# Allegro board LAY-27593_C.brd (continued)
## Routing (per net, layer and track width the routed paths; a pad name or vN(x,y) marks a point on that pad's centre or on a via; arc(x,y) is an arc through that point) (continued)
VREFH: length 2.7
  TOP w0.305: U7.37 20.5,24.35 20.57,24.42 v1(20.57,24.43)
  BOTTOM w0.61: C213.1 v1(20.57,24.43)
VREFL: length 3.4
  TOP w0.305: U7.38 21,23.79 21.65,24.43 v1(22.09,24.43)
  BOTTOM w0.61: v1(22.09,24.43) C212.1
N7254025: length 3
  BOTTOM w0.178: R200.2 63.36,52.01 J201.3
N7311373: length 8.9
  TOP w0.178: Q1.1 56.31,40.37 54.99,41.69 52.96,41.69 51.48,40.22 R9.2
  BOTTOM w0.178: R205.2 Q1.1
N7313274: length 3.5
  TOP w0.178: D4.A 60.75,39.8 R10.2
N7314056: length 70.4
  BOTTOM w0.178: R213.2 33.4,29.12 33.4,31.79 33.97,32.37 33.98,32.37 37.02,35.41 39.56,35.41 41.14,36.99 46.7,36.99 50.64,40.93 51.5,41.79 53.06,41.79 54.35,43.09 65.02,43.09 69.97,48.04 69.97,61.5 D2.C
N7314060: length 60.7
  TOP w0.178: v1(20.82,28.87) 20.32,29.37 19.05,29.37 v1(14.6,33.82)
  L3_PWR w0.178: D1.C 10.74,69.43 8.84,69.43 8.2,68.79 8.2,67.88 8.77,67.31 8.77,59.99 11.43,57.34 11.43,43.85 10.27,42.7 10.27,40.77 11.05,40 11.05,39.58 10.98,39.52 10.98,38.71 11.81,37.88 11.81,36.61 v1(14.6,33.82)
  BOTTOM w0.178: v1(20.82,28.87) 21.34,28.35 23.81,28.35 24.51,27.65 24.51,25.56 25.14,24.93 R216.2
N7317031: length 9
  TOP w0.889: U6.3 79.68,47.75 J1.1
N7317123: length 22.1
  TOP w0.178: U4.4 4.36,53.34 R3.1 4.36,55.33 7.04,58.01 10.97,58.01 13.64,55.34 13.85,55.03 13.85,51.73 12.84,50.72 v1(12.84,50.46)
  BOTTOM w0.178: J202.3 10.55,50.46 v1(12.84,50.46)
N7317135: length 2.9
  TOP w0.178: U3.2 9.89,52.83 11.73,54.67 R4.1
N7317139: length 7.7
  TOP w0.178: v1(7.97,57.44) 7.83,57.3 7.83,55.22 C3.2 R3.2
  BOTTOM w0.178: v1(7.97,57.44) 7.97,56.3 ; 7.97,56.3 D201.A ; 7.97,56.3 6.9,56.3 D200.A
N7317159: length 19.9
  TOP w0.178: v1(13.08,44.61) 13.08,44.66 12.26,45.47 12.26,50.82 12.6,51.15 12.63,51.15 13.49,52.01 13.49,54.92 13.36,55.11 12.84,55.64 10.77,55.64 10.27,55.14 10.27,54.86 R4.2 C3.1
  BOTTOM w0.178: J202.9 11.45,42.99 v1(13.08,44.61)
N7317195: length 26.3
  TOP w0.178: v1(3.68,57.58) 6.01,57.58 6.8,58.37 11.12,58.37 13.92,55.57 14.2,55.14 14.2,51.58 13.41,50.79 13.41,50.22 13.04,49.85 v1(13.04,45.51)
  BOTTOM w0.178: D200.C 3.68,56.37 v1(3.68,57.58) ; J202.7 13.02,45.53 v1(13.04,45.51)
N7317203: length 11.4
  BOTTOM w0.178: 14,50.23 13.22,51.01 13.22,53.36 12.29,54.29 D201.C ; 14,50.23 D202.A ; 14,50.23 14,50.11 13.2,49.31 12.82,49.31 11.58,48.07 J202.5
N7317219: length 2.8
  TOP w0.178: U4.3 v1(5.2,51.73)
  BOTTOM w0.178: J202.4 5.2,50.85 v1(5.2,51.73)
N7317435: length 1.8
  TOP w0.178: R11.2 79.8,36.51 U6.2
N7330976: length 9
  TOP w0.889: J1.2 77.14,47.75 U6.4
N7332359: length 2.1
  TOP w0.178: R7.2 5.76,42.67 U4.2
N7333527: length 4.5
  TOP w0.178: v1(12.92,54.75) 12.19,54.02 12.19,52.88 U3.1
  BOTTOM w0.178: D202.C 14.09,54.37 13.71,54.75 v1(12.92,54.75)
N7413835: length 2
  TOP w0.305: U5.1 43.36,42.27 43.81,41.82 C5.1
N7432331: length 3.7
  TOP w0.508: R14.2 R13.1
N7432681: length 3.7
  TOP w0.508: R15.2 R14.1
N7432685: length 8.3
  TOP w0.508: R12.2 62,30.01 60.96,28.97 R15.1
N7470913: length 19.8
  BOTTOM w0.635: 50.77,16.06 U200.7 47.47,16.06 ; 50.64,13.52 U200.5 47.47,13.52 ; 50.64,14.79 U200.6 47.47,14.79 ; 50.69,17.33 U200.8 47.52,17.33
  BOTTOM w0.889: C217.2 52.04,17.46 ; C217.2 R217.2 ; C217.2 51.02,19.37 C218.2 50.75,17.38 50.69,17.33
N7471057: length 2.1
  BOTTOM w0.635: C217.1 53.97,17.42 U200.1
N7471061: length 14.4
  BOTTOM w0.635: U200.2 55.39,16.06 55.75,16.42 55.75,20.36 54.86,21.25 54,21.25 R217.1 53.97,22.39 53.59,22.77 50.67,22.77 C216.2 50.75,22.44 R218.2
N7471069: length 7.2
  BOTTOM w0.889: D203.C 47.36,22.64 C216.1 48.81,22.44 R218.1 C218.1
N7676044: length 12.1
  TOP w0.508: U8.1 44.38,9.01 44.77,8.62 44.77,7.5 44.38,7.11 U8.3
  TOP w0.762: C24.1 43.82,9.03 U8.1
  TOP w0.889: C24.1 C23.1 40.18,12.05 39.34,12.89 J6.2
N7706869: length 4
  TOP w0.178: U7.25 12.19,24.42 10.38,26.22 Y1.1
N7742135: length 2.2
  TOP w0.762: D5.C 54.78,9.78 55.5,9.07 D6.1
N7743508: length 3.7
  TOP w0.762: R24.1 45.89,6.57 U8.4 47.61,7.11 R23.2
N7798929: length 43.4
  L3_PWR w0.178: v1(25.12,28.5) 26.05,28.5 26.67,29.12 27.49,29.12 27.94,28.67 27.94,27.47 29.61,25.79 v1(30.16,25.79)
  BOTTOM w0.229: R210.2 18.51,34.1 16.03,34.1 15.44,33.51 15.44,29.81 16,29.25 16.97,29.25 17.02,29.25 18.4,29.25 19.13,29.97 21.33,29.97 22.06,29.25 24.06,29.25 24.8,28.5 v1(25.12,28.5)
  BOTTOM w0.381: v1(30.16,25.79) 32.1,25.79 32.51,26.2 33.65,26.2 35.3,27.85 39.31,27.85 40.7,29.25 43.13,29.25 J4.1
N7799438: length 27.3
  BOTTOM w0.229: J3.1 40.11,27.49 38.8,26.18 36.34,26.18 34.46,24.3 28.9,24.3 27.89,25.31 25.52,25.31 24.89,25.94 24.89,27.81 23.94,28.76 21.79,28.76 21.08,29.48 19.91,29.48 R214.2
N7817781: length 5.9
  TOP w0.178: Y1.2 14.7,23.68 15,23.38 U7.26
N7845653: length 4.8
  TOP w0.889: J8.1 59.53,7.28 57.27,7.28 56.3,7.06 D6.3
N7881250: length 23.4
  TOP w0.508: J5.1 62.86,15.78 v1(65.15,15.78) v1(65.15,14.92)
  L3_PWR w0.508: v1(65.15,14.92) v1(65.15,15.78) 65.15,15.94 68.42,19.21 72.39,19.21 76.45,23.28 76.45,25.03 BT200.1
N8061225: length 18.1
  TOP w0.178: D3.C 33.7,43.55 32.89,44.36 26.29,44.36 26.16,44.23 23.49,44.23 23.36,44.36 22.2,44.36 21.84,44.72 v1(21.84,44.74)
  BOTTOM w0.178: v1(21.84,44.74) 21.84,44.69 21.64,44.49 21.64,42.42 20.95,41.74 20.95,40.62 21.22,40.36 21.22,40.23 R204.2
N8098939: length 12.5
  TOP w0.178: v1(27.06,41.55) 27.06,41.58 27.61,42.12 SW1.1 25.07,43.11 24.36,43.82 20.01,43.82 19.3,43.11 SW1.2
  BOTTOM w0.178: v1(27.06,41.55) R203.2

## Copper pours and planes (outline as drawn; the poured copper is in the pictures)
GND on TOP: 36.19,10.27 1.27,10.27 1.27,87.73 84.73,87.73 84.73,21.12 74.93,21.12 74.93,8.8 70.99,8.8 70.99,0.93 36.19,0.93 ; 12 cut-outs
GND on BOTTOM: 36.19,10.27 1.27,10.27 1.27,87.73 84.73,87.73 84.73,21.12 74.93,21.12 74.93,8.8 70.99,8.8 70.99,0.93 36.19,0.93 ; 20 cut-outs
GND on L2_GND: 74.04,1.69 36.72,1.69 36.69,10.44 2.03,10.44 2.03,28.61 13.08,28.61 14.47,30.01 14.47,35.85 10.66,39.66 10.66,42.33 13.2,45.38 13.71,46.01 17.27,46.01 17.9,45.38 17.9,40.3 18.92,39.28 27.56,39.28 28.44,40.42 28.44,50.96 30.22,52.74 53.59,52.74 56,54.77 56,73.57 57.65,75.35 70.1,75.35 70.1,87.41 83.97,87.41 83.97,21.12 74.04,21.12 ; 1 cut-out
VDD on TOP: 61.08,9.18 61.08,11.59 69.59,11.59 69.59,9.18
VDD on L3_PWR: 72.97,2.16 37.03,2.16 37,10.57 2.03,10.57 2.03,28.74 13.08,28.74 14.47,30.14 14.47,35.85 10.79,39.53 10.66,40.04 10.66,42.45 13.71,46.14 17.27,46.14 17.9,45.5 17.9,40.42 18.92,39.41 27.56,39.41 28.44,40.55 28.44,51.09 30.22,52.87 53.59,52.87 56,54.9 56,73.7 57.65,75.47 70.1,75.47 70.1,87.09 83.97,87.09 83.97,22.16 72.97,22.16
VDDA on TOP: 13.46,19.59 13.46,15.02 16.13,15.02 16.13,18.45 16.63,18.45 16.63,20.99 15.74,20.99 15.74,19.59
VDDA on L3_PWR: 16.89,24.45 16.89,20.89 5.84,20.86 5.84,13.5 21.71,13.5 21.71,12.86 26.79,12.86 26.72,19.87 18.72,19.87 18.72,21.65 18.33,21.65 18.33,23.68 18.72,23.68 18.72,24.45
VIN on BOTTOM: 65.27,30.01 65.27,23.4 67.56,23.4 67.56,16.42 71.12,16.42 71.12,19.34 71.37,19.34 71.37,22.52 75.82,22.52 75.82,30.01
VOUT on BOTTOM: 35.81,23.28 35.81,17.05 40.76,17.05 40.76,12.61 43.18,12.61 43.18,23.28
N7470913 on BOTTOM: 40.51,9.18 40.51,10.96 45.08,10.96 45.08,19.34 47.49,19.34 47.49,18.07 52.45,18.07 52.45,15.15 51.05,15.15 51.05,11.09 48.64,11.09 48.64,9.18
N7471025 on BOTTOM: 60.83,22.39 60.83,10.2 63.5,10.2 63.5,16.42 65.66,16.42 65.66,18.58 65.15,18.58 65.15,22.39
N7471045 on BOTTOM: 58.92,22.39 58.92,5.88 51.81,5.88 51.81,9.31 52.96,9.31 52.96,13.88 56.51,13.88 56.51,22.39

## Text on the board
BOTTOM: 7 OF 10 | SECONDARY SIDE | 170-27593 REV C
Board Geometry/Soldermask Bottom: 8 OF 10 | SECONDARY SOLDERMASK
Ref Des/Silkscreen Bottom: RF | VOUT | GND | UMI | VIN | RS232 | 9 OF 10 | SECONDARY SILKSCREEN | L | N
User.Comments: 1 OF 1 | TEST PROBE | 1/1 | 1
TOP: 4 OF 10 | PRIMARY SIDE
Board Geometry/Soldermask Top: 3 OF 10 | PRIMARY SOLDERMASK
Ref Des/Silkscreen Top: RES_OUT->1 | RES_INP->2 | VDDA | INFRARED | 2 | SAR | J7 CFG: | TP6 | kVARh | USER | VOUT | GND | JUMPER | PSU | VPWR | TAMPER2 | TAMPER1 | MCU | VBAT | VDD | BATT | VIN | PULSE_OUT | kWh | DEBUG | 1PHMET-KM34Z128 | 2 OF 10 | PRIMARY SILKSCREEN | L | N
L2_GND: 5 OF 10 | GROUND PLANE
L3_PWR: 6 OF 10 | POWER PLANE
DIMENSION: PRIMARY DATUM | GRID ORIGIN | VIEW FROM PRIMARY SIDE
PLACE_BOUND_TOP: 16 | 17 | 8
User.5: 1 OF 10 | PRIMARY SOLDER PASTE
User.6: 10 OF 10 | SECONDARY SOLDER PASTE
User.19: 04-30-13 | 12-14-12 | 12-17-12 | M.B. | B | B1 | C | Re-Spin Per ECO40607 | MOVED SW1 1 MM TO THE LEFT | CHANGES AS PER ECOXXXXX
User.23: FIGURE | SIZE | 12.0 | 38.0 | 40.0 | 44.0 | 45.0 | 51.0 | 138.0 | DRILL CHART: TOP to BOTTOM | ALL UNITS ARE IN MILS | TOLERANCE | +0.0/-12.0 | +3.0/-3.0 | +2.0/-2.0 | PLATED | NON-PLATED | QTY | 262 | 28 | 16 | 4 | 3 | 2
